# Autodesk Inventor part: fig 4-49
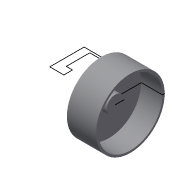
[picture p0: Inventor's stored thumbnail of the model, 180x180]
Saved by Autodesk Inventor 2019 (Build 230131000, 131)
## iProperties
Created: 2004-05
Part Number: fig 4-49
Document SubType Name: Modeling
Designer: CADCIM Technologies
Manufacturer: Standard
Standards Organization: Custom
Density: 1 g/cm^3
Material: Generic
Appearance: Default
Author: CADCIM Technologies
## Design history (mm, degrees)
sketch "Sketch1"
  geometry: L1 (37.08, 12.209)-(23.643, 12.209); L2 (23.643, 12.209)-(23.643, 45.026); L3 (23.643, 45.026)-(51.55, 45.026); L4 (51.55, 45.026)-(51.55, 42.959); L5 (51.55, 42.959)-(31.137, 42.959); L6 (31.137, 42.959)-(31.137, 20.478); L7 (31.137, 20.478)-(37.08, 20.478); L8 (37.08, 20.478)-(37.08, 12.209); L9 (86.437, 12.209)-(73, 12.209); L10 (73, 12.209)-(73, 45.026); L11 (73, 45.026)-(100.907, 45.026); L12 (100.907, 45.026)-(100.907, 42.959); L13 (100.907, 42.959)-(80.494, 42.959); L14 (80.494, 42.959)-(80.494, 20.478); L15 (80.494, 20.478)-(86.437, 20.478); L16 (86.437, 20.478)-(86.437, 12.209)
  constraints: 32 end point, 12 parallel, 2 horizontal, 2 perpendicular
revolve "Revolution1" sketch "Sketch1" stored, may be unused: angle "d0" = 90 deg
body "Solid1"
